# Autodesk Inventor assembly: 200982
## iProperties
Created: 2007-12
Part Number: 200982
Document SubType Name: Assembly
Designer: MM
Mass: 639.266 g
Surface Area: 331.471 cm^2
Volume: 81.5803 cm^3
Density: 7.83603 g/cm^3
Description: FRONT PIVOT LINK ASSEMBLY
Component Category: Lower Component
Author: MM
